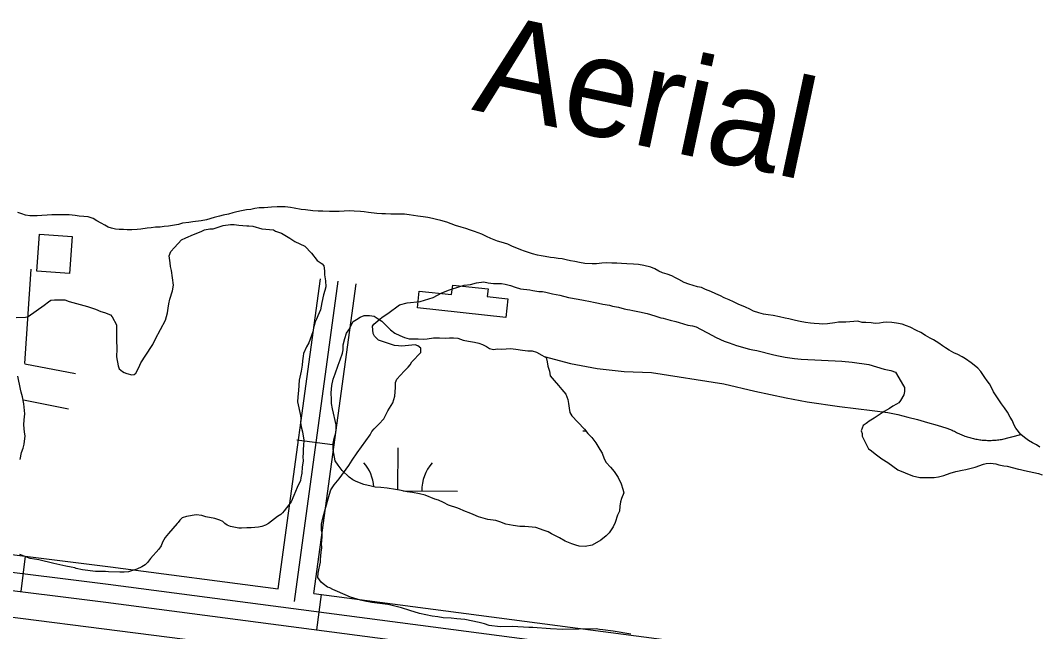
# Model space of a CAD drawing. Extents: x 3161514 to 3199414, y 831166 to 856601.
# Drawn here: x 3186690 to 3187544, y 849984 to 850496 of the extents above; entities that cross this region are included whole.
import ezdxf

# ---------------------------------------------------------------- set-up
doc = ezdxf.new("R2010")
doc.units = 0
for name, color, linetype in [('V-BLDG-OTLN', 7, 'Continuous'), ('V-LEVE-TOET', 7, 'Continuous'), ('V-RIVR-IDEN', 7, 'Continuous'), ('V-ROAD-CNTR', 7, 'Continuous'), ('V-SITE-VEGE', 7, 'Continuous'), ('V-TOPO-SHOR', 7, 'Continuous'), ('V-WETL-SWMP', 7, 'Continuous')]:
    doc.layers.add(name, color=color, linetype=linetype)

msp = doc.modelspace()

# ---------------------------------------------------------------- linework, layer by layer
at = {"layer": 'V-BLDG-OTLN'}
for points in [[(3186704.25, 850285.64), (3186706.49, 850316.62), (3186733.69, 850314.67), (3186731.46, 850283.68)], [(3187097.06, 850246.78), (3187022.99, 850254.86), (3187024.54, 850269.01), (3187051.6, 850266.06), (3187052.47, 850274.07), (3187082.15, 850270.83), (3187081.46, 850264.47), (3187098.79, 850262.58)]]:
    msp.add_lwpolyline(points, close=True, dxfattribs=at)
at = {"layer": 'V-LEVE-TOET'}
msp.add_lwpolyline([(3185951.2, 850091.7), (3186111.35, 850071.25), (3186287.91, 850050.19), (3186449.48, 850029.4), (3186609.3, 850005.42), (3186841.67, 849975.68), (3187036.96, 849950.67), (3187260.69, 849919.64), (3187537.4, 849882.56), (3187802.62, 849847.53), (3188050, 849815.58), (3188330.04, 849780.64), (3188583.22, 849752.07), (3188616.24, 849747.31), (3188633.9, 849745.47), (3188641.14, 849745.34)], dxfattribs=at)
at = {"layer": 'V-ROAD-CNTR'}
for p, q in [((3186694.27, 850208.45), (3186699.57, 850287.45)), ((3186922.05, 850144.5), (3186951.77, 850140.44)), ((3186694.39, 850046.98), (3186690.68, 850017.21)), ((3186942.42, 850014.88), (3186938.51, 849985.14))]:
    msp.add_line(p, q, dxfattribs=at)
for points in [[(3186906.31, 850019.62), (3186941.81, 850279.21)], [(3186919.98, 850008.84), (3186956.67, 850277.18)], [(3186936.06, 850015.71), (3186971.54, 850275.15)], [(3186694.3, 850208.08), (3186736.48, 850199.92)], [(3189447.95, 850001.11), (3189429.03, 849814.74), (3189421.01, 849784.3), (3189410.76, 849768.58), (3189395.7, 849753.5), (3189376.92, 849738.22), (3189354.56, 849730.31), (3189331.81, 849725.77), (3189310.92, 849725.82), (3189278.4, 849725.99), (3188774.4, 849761.57), (3188653.34, 849778.2), (3188289.25, 849825.21), (3187591.11, 849914.58), (3186763.92, 850023.19), (3186125.42, 850102.82), (3185403.58, 850201)], [(3185401.56, 850186.13), (3186123.48, 850087.95), (3186762.01, 850008.31), (3187589.18, 849899.7), (3188287.33, 849810.33), (3188617.05, 849767.76)], [(3186693.09, 850177.76), (3186730.79, 850170.47)], [(3186683.41, 850048.35), (3186765.82, 850038.07), (3186906.31, 850019.62)], [(3186936.06, 850015.71), (3187593.04, 849929.45), (3187874.08, 849893.48)]]:
    msp.add_lwpolyline(points, dxfattribs=at)
at = {"layer": 'V-SITE-VEGE'}
for points in [[(3186686.89, 850246.9), (3186694.82, 850247.18), (3186696.91, 850247.66), (3186710.38, 850257.06), (3186713.86, 850260.11), (3186715.95, 850261.29), (3186718.98, 850261.77), (3186722.24, 850261.79), (3186727.6, 850261.58), (3186731.34, 850260.21), (3186746.75, 850256.1), (3186753.29, 850253.81), (3186757.73, 850251.97), (3186761, 850251.05), (3186765.9, 850248.98), (3186767.31, 850247.36), (3186770.85, 850240.62), (3186770.92, 850228.03), (3186771.19, 850220.57), (3186771, 850213.81), (3186772.2, 850206.36), (3186773.15, 850203.8), (3186775.96, 850201.72), (3186777.36, 850200.79), (3186779.7, 850199.88), (3186783.9, 850198.73), (3186785.77, 850198.98), (3186787.16, 850200.15), (3186789.69, 850205.06), (3186791.31, 850208.8), (3186800.32, 850222.6), (3186801.48, 850224.24), (3186803.55, 850228.91), (3186811.85, 850244.58), (3186813.68, 850250.65), (3186814.12, 850254.62), (3186814.8, 850258.35), (3186815.71, 850262.32), (3186817.77, 850269.32), (3186818.68, 850273.99), (3186816.98, 850286.1), (3186816.03, 850289.59), (3186816.01, 850292.62), (3186815.04, 850298.44), (3186816.42, 850302.18), (3186819.43, 850305.46), (3186825.46, 850312.02), (3186828.94, 850313.67), (3186835.46, 850316.51), (3186841.73, 850318.88), (3186844.52, 850320.29), (3186849.19, 850321.01), (3186851.98, 850321.03), (3186860.35, 850323.88), (3186866.41, 850324.84), (3186869.44, 850324.62), (3186873.41, 850324.18), (3186880.17, 850323.75), (3186881.8, 850323.76), (3186885.07, 850323.32), (3186892.54, 850321.26), (3186902.33, 850320.15), (3186904.2, 850319.23), (3186909.11, 850317.62), (3186916.13, 850313.23)], [(3186916.13, 850313.23), (3186920.34, 850310.46), (3186928.52, 850306.54), (3186934.15, 850300.75), (3186939.08, 850294.72), (3186943.29, 850291.94), (3186944.46, 850290.08), (3186945.19, 850285.89), (3186945.21, 850282.63), (3186945.93, 850277.5), (3186946.19, 850272.61), (3186945.28, 850269.57), (3186944.37, 850265.84), (3186943, 850259.54), (3186941.87, 850253.24), (3186939.57, 850248.33), (3186938.42, 850245.53), (3186937.27, 850243.19), (3186936.59, 850240.16), (3186935.9, 850238.05), (3186935.22, 850234.79), (3186932.01, 850225.68), (3186930.16, 850222.41), (3186927.63, 850216.79), (3186927.18, 850214.46), (3186926.73, 850210.49), (3186926.52, 850207), (3186925.61, 850201.86), (3186924.02, 850194.39), (3186923.37, 850185.77), (3186922.7, 850180.4), (3186922.5, 850176.2), (3186924.89, 850164.8), (3186925.37, 850162), (3186925.16, 850158.97), (3186925.65, 850155.24), (3186926.83, 850151.05), (3186927.81, 850144.07), (3186927.6, 850139.64), (3186927.15, 850136.6), (3186927.17, 850133.34), (3186926.95, 850130.08), (3186927.2, 850126.81), (3186926.3, 850121.45), (3186926.1, 850116.55), (3186925.19, 850112.58)], [(3187004.71, 850188.32), (3187004.46, 850192.29), (3187005.84, 850195.09), (3187011.86, 850201.88), (3187015.11, 850205.17), (3187016.73, 850207.27), (3187018.35, 850209.61), (3187025.76, 850217.58), (3187025.74, 850221.08), (3187023.16, 850223.16), (3187021.06, 850223.85), (3187009.88, 850222.85), (3187007.08, 850223.07), (3187003.81, 850223.52), (3186990.27, 850227.87), (3186986.99, 850231.11), (3186985.81, 850233.44), (3186985.31, 850239.73), (3186986.46, 850241.37), (3186991.34, 850245.36), (3186993.43, 850247), (3186998.07, 850250.29), (3187008.05, 850257.57), (3187014.34, 850259.01), (3187025.29, 850260.24), (3187036.22, 850263.56), (3187043.43, 850267.56), (3187049.94, 850270.16), (3187058.55, 850272.78), (3187062.04, 850273.96), (3187067.4, 850274.46), (3187072.29, 850275.88), (3187078.58, 850276.62), (3187082.31, 850275.94), (3187086.74, 850275.27), (3187093.27, 850275.31), (3187096.53, 850274.86), (3187100.97, 850273.71), (3187104.71, 850272.34), (3187109.38, 850270.96), (3187117.08, 850270.08), (3187119.64, 850269.39), (3187124.54, 850268.72), (3187127.81, 850268.74), (3187130.61, 850268.06), (3187135.97, 850266.69), (3187142.28, 850265.56), (3187149.51, 850263.73), (3187157.68, 850262.15), (3187162.11, 850261.47), (3187167.95, 850260.34), (3187170.52, 850259.66), (3187174.72, 850258.75), (3187178.22, 850258.07), (3187183.82, 850257.17), (3187186.38, 850256.48), (3187191.29, 850255.58), (3187195.95, 850254.2), (3187198.76, 850253.52), (3187200.85, 850253.3), (3187203.42, 850252.85), (3187209.02, 850251.48), (3187215.32, 850250.12), (3187221.86, 850248.29), (3187226.77, 850246.69), (3187228.87, 850246.23), (3187234.7, 850244.63), (3187239.37, 850243.49), (3187242.18, 850242.58), (3187245.91, 850241.67), (3187249.41, 850240.52), (3187253.38, 850239.84), (3187256.42, 850238.93), (3187259.92, 850237.08), (3187266, 850234.09), (3187273.25, 850230.17), (3187279.79, 850226.94), (3187284, 850225.56), (3187290.3, 850223.27), (3187301.04, 850220.3), (3187303.84, 850219.85), (3187307.11, 850219.17), (3187321.35, 850215.52), (3187325.32, 850214.61), (3187330.92, 850213.71), (3187338.85, 850212.59), (3187344.45, 850211.92), (3187378.26, 850210.24), (3187387.12, 850209.36), (3187401.12, 850207.35), (3187413.96, 850203.69), (3187419.33, 850202.55), (3187423.3, 850201.17), (3187429.89, 850189.56), (3187430.83, 850188.16), (3187430.85, 850184.9), (3187430.17, 850182.1), (3187427.63, 850177.42), (3187426.01, 850175.32), (3187424.15, 850174.14), (3187421.13, 850172.49)], [(3186690.13, 850128.04), (3186691.26, 850133.64), (3186692.64, 850137.38), (3186693.55, 850140.88), (3186694.45, 850147.65), (3186693.96, 850150.9), (3186693.46, 850156.96), (3186693.67, 850161.16), (3186694.11, 850166.29), (3186693.36, 850174.45), (3186692.17, 850180.27), (3186691.21, 850184.22), (3186690.5, 850186.78), (3186688.33, 850197.73)], [(3187201.69, 849981.51), (3187186.99, 849983.98), (3187178.12, 849985.33), (3187175.33, 849985.55), (3187172.52, 849986), (3187158.07, 849985.92), (3187144.79, 849985.61), (3187134.53, 849986.02), (3187119.6, 849987.1), (3187116.11, 849987.08), (3187102.58, 849987.94), (3187092.33, 849987.88), (3187083, 849988.99), (3187079.03, 849990.37), (3187074.59, 849991.51), (3187062.69, 849994.01), (3187055.92, 849994.43), (3187051.26, 849994.87), (3187044.5, 849995.3), (3187040.06, 849996.21), (3187035.4, 849996.65), (3187024.66, 849998.92), (3187016.49, 850001.44), (3187009.48, 850003.73), (3187007.39, 850004.18), (3187000.61, 850006.01), (3186998.28, 850006.46), (3186984.75, 850008.25), (3186978.92, 850009.15), (3186975.18, 850010.06), (3186966.78, 850012.58), (3186956.03, 850017.41), (3186952.05, 850019.02), (3186949.71, 850020.41), (3186947.61, 850021.1), (3186944.1, 850023.87), (3186942.46, 850025.03), (3186939.64, 850028.98), (3186939.86, 850032.71), (3186940.31, 850035.51), (3186941.22, 850039.47), (3186941.67, 850042.04), (3186941.89, 850044.14), (3186942.32, 850050.21), (3186942.77, 850053.94), (3186942.75, 850057.43), (3186942.97, 850059.53), (3186943.18, 850063.5), (3186943.16, 850066.29), (3186942.68, 850068.85), (3186942.65, 850073.75), (3186943.79, 850078.65), (3186946.3, 850087.99), (3186948.13, 850094.99), (3186949.27, 850098.96), (3186950.42, 850102.46), (3186953.19, 850106.68), (3186957.36, 850111.83), (3186965.45, 850122.83), (3186968.23, 850127.28), (3186972.62, 850133.36), (3186983.25, 850148.57), (3186984.88, 850151.38), (3186986.73, 850153.49), (3186990.67, 850157.47), (3186994.84, 850161.93), (3186998.3, 850168.7), (3187002.22, 850175.26), (3187004.05, 850181.09), (3187004.71, 850188.32)], [(3187421.13, 850172.49), (3187418.34, 850170.61), (3187413.93, 850168.02), (3187405.33, 850162.61), (3187401.39, 850160.03), (3187399.99, 850158.85), (3187398.83, 850158.15), (3187396.28, 850156.27), (3187394.44, 850151.83)], [(3187394.44, 850151.83), (3187395.38, 850149.73), (3187395.4, 850147.4), (3187400.82, 850136.94), (3187402.22, 850136.02), (3187407.37, 850131.85), (3187411.82, 850128.38), (3187416.97, 850125.38), (3187425.39, 850119.37), (3187437.54, 850114.31), (3187443.61, 850112.94), (3187452.94, 850112.76), (3187455.73, 850112.78), (3187459.23, 850113.26), (3187463.88, 850114.46), (3187469, 850116.58), (3187473.89, 850117.78), (3187475.28, 850118.25), (3187479.24, 850118.97), (3187482.27, 850119.45), (3187489.95, 850121.59), (3187496.93, 850123.97), (3187499.26, 850124.68), (3187502.75, 850124.93), (3187507.42, 850124.26), (3187509.98, 850123.57), (3187513.95, 850122.66), (3187516.75, 850122.21), (3187526.33, 850119.7), (3187527.96, 850119.48), (3187531.46, 850118.57), (3187543.13, 850116.07), (3187546.16, 850115.15)], [(3186925.19, 850112.58), (3186924.96, 850110.25), (3186922.2, 850104.41), (3186919.44, 850097.86), (3186917.14, 850092.49), (3186915.29, 850089.91), (3186911.35, 850085), (3186909.96, 850083.12), (3186908.58, 850081.95), (3186905.79, 850080.3), (3186898.13, 850074.43), (3186895.8, 850073.02), (3186892.78, 850071.84), (3186889.75, 850071.35), (3186883.7, 850070.62), (3186879.97, 850070.6), (3186875.54, 850070.34), (3186873.44, 850070.33), (3186866.44, 850071.69), (3186863.64, 850072.84), (3186861.76, 850074.23), (3186860.12, 850075.85), (3186857.55, 850077.23), (3186853.35, 850078.61), (3186845.88, 850079.96), (3186842.38, 850080.88), (3186837.71, 850081.55), (3186829.56, 850080.11), (3186825.84, 850078.92), (3186823.99, 850077.04), (3186822.6, 850075.17), (3186821.67, 850074.23), (3186814.49, 850066.03), (3186811.71, 850062.52), (3186809.4, 850058.78), (3186808.25, 850055.51), (3186806.41, 850052.7), (3186799.46, 850044.97), (3186796.91, 850041.69), (3186794.83, 850039.58), (3186792.04, 850037.94), (3186788.08, 850036.05), (3186781.1, 850033.68), (3186777.37, 850033.42), (3186773.65, 850033.4), (3186764.32, 850033.82), (3186761.76, 850034.03), (3186759.19, 850034.02), (3186755.46, 850034.23), (3186753.36, 850033.99), (3186742.4, 850035.56), (3186737.26, 850036.69), (3186736.1, 850037.15), (3186733.06, 850037.83), (3186728.4, 850038.51), (3186718.36, 850040.78), (3186705.75, 850043.97), (3186698.75, 850045.1), (3186690.11, 850048.32)]]:
    msp.add_lwpolyline(points, dxfattribs=at)
at = {"layer": 'V-TOPO-SHOR'}
msp.add_line((3187511.98, 850144.71), (3187528.17, 850148.98), dxfattribs=at)
for points in [[(3187218.44, 850288.95), (3187212.5, 850290.52), (3187208, 850291.14), (3187203.98, 850291.44), (3187198.37, 850291.88), (3187193.87, 850292.02), (3187190.02, 850292.32), (3187185.85, 850292.46), (3187181.67, 850292.59), (3187177.5, 850292.41), (3187173.01, 850291.9), (3187169.16, 850291.72), (3187163.06, 850292.17), (3187158.72, 850292.94), (3187154.86, 850293.88), (3187151.01, 850294.34), (3187147.47, 850295.29), (3187144.1, 850296.07), (3187140.89, 850296.21), (3187137.51, 850296.83), (3187134.3, 850297.14), (3187129.8, 850297.92), (3187126.59, 850298.54), (3187123.54, 850299.17), (3187119.36, 850300.1), (3187115.98, 850301.37), (3187112.61, 850302.47), (3187109.55, 850303.58), (3187106.33, 850305.01), (3187102.47, 850306.43), (3187098.61, 850308.17), (3187093.15, 850309.91), (3187090.09, 850310.69), (3187084.3, 850312.91), (3187080.92, 850314.65), (3187076.9, 850316.56), (3187073.68, 850317.66), (3187070.63, 850318.93), (3187067.41, 850320.03), (3187063.55, 850321.45), (3187059.69, 850322.56), (3187054.71, 850323.97), (3187051.33, 850325.4), (3187047.47, 850326.66), (3187042.65, 850328.08), (3187038.95, 850329.02), (3187035.58, 850329.64), (3187031.56, 850330.58), (3187027.71, 850331.2), (3187023.37, 850331.66), (3187016.14, 850332.74), (3187012.13, 850333.36), (3187008.6, 850333.5), (3187004.9, 850333.48), (3187000.57, 850333.46), (3186996.08, 850333.59), (3186993.03, 850333.73), (3186988.85, 850334.03), (3186981.95, 850334.8), (3186978.41, 850335.26), (3186975.2, 850335.56), (3186969.9, 850336.01), (3186966.21, 850336.15), (3186961.72, 850335.97), (3186957.39, 850335.62), (3186953.86, 850335.76), (3186949.36, 850335.73), (3186943.75, 850336.03), (3186939.73, 850336), (3186935.4, 850336.3), (3186929.3, 850336.91), (3186925.6, 850337.37), (3186919.82, 850338.46), (3186916.77, 850339.08), (3186912.27, 850339.54), (3186908.74, 850339.52), (3186905.53, 850339.5), (3186900.72, 850339.15), (3186897.67, 850338.97), (3186894.62, 850338.8), (3186890.29, 850338.61), (3186886.92, 850338.11), (3186883.55, 850337.45), (3186879.7, 850337.11), (3186875.54, 850336.28), (3186871.69, 850335.3), (3186868.48, 850334.48), (3186864.8, 850333.49), (3186860.31, 850332.67), (3186857.26, 850331.85), (3186852.62, 850330.54), (3186846.21, 850328.57), (3186841.88, 850327.75), (3186834.99, 850327.07), (3186831.46, 850326.56), (3186826.33, 850325.73), (3186822.8, 850324.75), (3186817.83, 850323.92), (3186814.62, 850323.42), (3186810.77, 850323.08), (3186807.41, 850322.42)], [(3186807.41, 850322.42), (3186803.71, 850322.4), (3186799.87, 850321.89), (3186796.66, 850321.56), (3186791.21, 850320.88), (3186788.16, 850320.7), (3186783.67, 850320.36), (3186779.81, 850320.33), (3186776.77, 850320.48), (3186773.23, 850320.62), (3186770.02, 850320.92), (3186766.81, 850321.71), (3186763.91, 850322.65), (3186761.18, 850324.08), (3186758.12, 850325.83), (3186754.58, 850327.9), (3186751.52, 850329.64), (3186747.18, 850331.06), (3186743.64, 850331.53), (3186739.63, 850331.82), (3186736.26, 850332.29), (3186731.28, 850332.9), (3186726.46, 850332.87), (3186722.61, 850332.85), (3186716.67, 850332.82), (3186712.98, 850332.64), (3186708.49, 850332.29), (3186704.48, 850331.95), (3186701.43, 850331.93), (3186698.38, 850331.91), (3186694.85, 850332.7), (3186691.63, 850333.64), (3186688.42, 850334.91)], [(3187544.12, 850138.32), (3187541.38, 850140.07), (3187538.16, 850141.98), (3187534.78, 850143.89), (3187531.4, 850146.28), (3187528.17, 850148.98), (3187524.13, 850154.26), (3187522.35, 850157.3), (3187521.21, 850160.18), (3187519.42, 850163.38), (3187517.15, 850167.54), (3187514.73, 850171.06), (3187512.14, 850174.57), (3187510.52, 850177.13), (3187508.25, 850180.33), (3187505.5, 850184.65), (3187503.88, 850187.69), (3187502.09, 850191.37), (3187500.15, 850193.92), (3187498.05, 850196.64), (3187494.81, 850201.6), (3187492.23, 850204.47), (3187489.17, 850206.86), (3187486.59, 850208.93), (3187482.07, 850212.28), (3187479.18, 850213.87), (3187475.64, 850215.77), (3187472.26, 850217.36), (3187468.39, 850219.58), (3187465.33, 850221.33), (3187462.6, 850223.08), (3187459.53, 850225.31), (3187455.19, 850228.01), (3187452.29, 850229.6), (3187448.42, 850231.83), (3187444.4, 850234.37), (3187440.86, 850235.96), (3187435.55, 850238.66), (3187432.49, 850239.92), (3187428.95, 850241.35), (3187424.29, 850242.12), (3187420.28, 850242.74), (3187416.1, 850242.88), (3187412.9, 850242.7), (3187409.85, 850242.04), (3187406.16, 850241.86), (3187402.95, 850242.32), (3187398.61, 850242.62), (3187395.4, 850242.76), (3187391.86, 850243.71), (3187388.5, 850243.37), (3187385.13, 850243.35), (3187381.76, 850243.01), (3187375.66, 850242.81), (3187372.61, 850242.47), (3187366.36, 850241.48), (3187362.51, 850241.13), (3187359.3, 850241.44), (3187355.28, 850241.73), (3187352.23, 850242.04), (3187347.9, 850242.66), (3187343.4, 850243.59), (3187339.7, 850244.21), (3187334.08, 850245.63), (3187331.02, 850246.41), (3187326.21, 850247.51), (3187320.74, 850248.6), (3187316.57, 850249.06), (3187312.71, 850249.68), (3187308.85, 850250.78), (3187304.51, 850252.2), (3187301.29, 850253.79), (3187297.59, 850255.53), (3187291.64, 850258.07), (3187287.78, 850259.97), (3187283.92, 850261.55), (3187279.89, 850263.46), (3187276.67, 850264.88), (3187272.81, 850266.79), (3187268.63, 850268.69), (3187264.29, 850270.43), (3187260.91, 850271.86), (3187257.53, 850272.64), (3187253.84, 850273.58), (3187250.14, 850274.84), (3187246.44, 850276.27), (3187241.93, 850278.81), (3187239.2, 850280.08), (3187235.98, 850281.66), (3187232.12, 850283.09), (3187228.1, 850284.35), (3187225.04, 850285.77), (3187221.66, 850287.52), (3187218.44, 850288.95)], [(3187129.01, 850214.29), (3187151.02, 850208.34), (3187173.41, 850204.09), (3187196.07, 850201.58), (3187218.85, 850200.82), (3187218.85, 850200.82), (3187279.6, 850191.23), (3187279.6, 850191.23), (3187305.64, 850185.21), (3187331.77, 850179.63), (3187349.21, 850176.17), (3187349.21, 850176.17), (3187376.47, 850172.27), (3187403.79, 850168.84), (3187416.95, 850167.35), (3187416.95, 850167.35), (3187425.28, 850165.49), (3187433.58, 850163.48), (3187441.83, 850161.33), (3187450.06, 850159.03), (3187458.24, 850156.6), (3187466.38, 850154.02), (3187470.74, 850152.57), (3187470.74, 850152.57), (3187471.66, 850152.04), (3187472.6, 850151.51), (3187473.54, 850151), (3187474.49, 850150.51), (3187475.46, 850150.04), (3187476.42, 850149.58), (3187477.4, 850149.14), (3187478.38, 850148.72), (3187479.38, 850148.31), (3187480.37, 850147.92), (3187481.38, 850147.55), (3187482.39, 850147.2), (3187483.41, 850146.86), (3187484.43, 850146.54), (3187485.46, 850146.24), (3187486.49, 850145.96), (3187487.53, 850145.7), (3187488.57, 850145.45), (3187489.62, 850145.22), (3187490.67, 850145.01), (3187491.72, 850144.82), (3187492.78, 850144.65), (3187493.84, 850144.49), (3187494.9, 850144.36), (3187495.97, 850144.24), (3187497.03, 850144.14), (3187498.1, 850144.06), (3187499.17, 850144), (3187500.24, 850143.95), (3187501.31, 850143.93), (3187502.38, 850143.92), (3187503.45, 850143.94), (3187504.52, 850143.97), (3187505.59, 850144.02), (3187506.66, 850144.09), (3187507.73, 850144.18), (3187508.8, 850144.28), (3187509.86, 850144.41), (3187510.92, 850144.55), (3187511.98, 850144.71), (3187511.98, 850144.71)]]:
    msp.add_lwpolyline(points, dxfattribs=at)
at = {"layer": 'V-WETL-SWMP'}
for p, q in [((3187161.35, 850151.98), (3187163.81, 850151.97)), ((3187006.62, 850102.49), (3187006.72, 850137.66)), ((3187011.1, 850101.65), (3187056.62, 850101.52))]:
    msp.add_line(p, q, dxfattribs=at)
for points in [[(3186951.88, 850170.47), (3186951.11, 850174.88), (3186951.1, 850178.19), (3186950.7, 850183.71), (3186951.4, 850189.96), (3186952.47, 850195.12), (3186953.92, 850199.54), (3186956.45, 850206.91), (3186958.27, 850211.34), (3186960.07, 850216.87), (3186960.79, 850219.81), (3186960.77, 850223.86), (3186962.21, 850229.39), (3186963.66, 850233.81), (3186965.48, 850236.39), (3186969.12, 850243.4), (3186972.05, 850245.26), (3186974.98, 850247.11), (3186978.29, 850248.6), (3186982.7, 850248.63), (3186986.75, 850247.92), (3186990.08, 850245.73), (3186993.03, 850243.91), (3186998.21, 850238.79), (3187000.43, 850236.59), (3187004.12, 850233.67), (3187008.18, 850231.85), (3187012.24, 850230.04), (3187015.92, 850228.95), (3187023.65, 850229), (3187027.69, 850228.65), (3187031, 850229.04), (3187036.52, 850229.81), (3187041.3, 850229.83), (3187046.08, 850229.49), (3187049.76, 850229.88), (3187053.07, 850229.9), (3187056.75, 850229.55), (3187061.18, 850227.74), (3187065.59, 850227.03), (3187070.75, 850226.32), (3187074.43, 850225.24), (3187077.38, 850224.15), (3187080.7, 850222.7), (3187083.29, 850220.87), (3187086.6, 850220.16), (3187089.91, 850220.54), (3187093.59, 850220.19), (3187097.27, 850220.58), (3187100.94, 850220.97), (3187105.36, 850220.26), (3187110.88, 850219.56), (3187115.3, 850218.84), (3187118.98, 850218.87), (3187122.67, 850217.78), (3187127.09, 850215.23), (3187129.01, 850214.29), (3187130.78, 850213.42), (3187131.54, 850209.74), (3187132.29, 850206.07), (3187133.42, 850202.03), (3187134.18, 850197.98), (3187137.51, 850193.96), (3187141.21, 850189.93), (3187143.81, 850186.63), (3187147.14, 850182.61), (3187149.01, 850178.2), (3187149.39, 850174.89), (3187150.15, 850170.85), (3187150.54, 850167.18), (3187152.39, 850164.61), (3187157.21, 850159.12), (3187162.76, 850153.27), (3187165.72, 850149.6), (3187169.05, 850146.31), (3187172.39, 850141.92), (3187175.73, 850136.42), (3187177.59, 850133.12), (3187179.45, 850128.34), (3187180.94, 850125.41), (3187184.64, 850121.39), (3187187.61, 850117.72), (3187190.94, 850112.96), (3187193.55, 850107.46), (3187195.05, 850103.05), (3187195.8, 850100.11), (3187193.99, 850095.32), (3187192.9, 850092.37), (3187192.55, 850088.69), (3187192.21, 850084.64), (3187190.39, 850081.32), (3187188.58, 850075.06), (3187186.76, 850071.37), (3187183.48, 850066.57), (3187180.92, 850063.98), (3187176.53, 850060.27), (3187169.19, 850056.19), (3187163.31, 850055.05), (3187158.53, 850055.39), (3187155.58, 850056.11), (3187152.26, 850057.19)], [(3187152.26, 850057.19), (3187146.73, 850059.37), (3187141.94, 850062.29), (3187135.29, 850065.56), (3187132.34, 850067.38), (3187129.02, 850068.47), (3187122.02, 850071), (3187112.82, 850071.69), (3187108.77, 850071.66), (3187103.25, 850072.73), (3187096.99, 850073.8), (3187091.83, 850075.61), (3187088.51, 850076.7), (3187081.89, 850077.77), (3187074.15, 850079.93), (3187069.72, 850081.74), (3187066.41, 850083.2), (3187063.09, 850084.28), (3187056.82, 850087.19), (3187049.08, 850089.72), (3187044.65, 850091.9), (3187040.6, 850093.72), (3187037.65, 850094.81), (3187029.54, 850098.07), (3187024.75, 850099.15), (3187018.85, 850100.22), (3187014.44, 850100.93), (3187007.81, 850102.36), (3187004.49, 850102.71), (3186997.5, 850103.78), (3186992.34, 850104.48), (3186987.56, 850104.82), (3186984.25, 850105.54), (3186977.98, 850106.97), (3186971.71, 850109.52), (3186968.76, 850110.97), (3186965.81, 850113.16), (3186959.89, 850118.65), (3186956.56, 850123.04), (3186953.96, 850126.7), (3186952.82, 850132.95), (3186952.44, 850136.26), (3186952.41, 850141.41), (3186953.12, 850145.46), (3186954.56, 850150.25), (3186954.91, 850153.56), (3186954.89, 850156.88), (3186951.88, 850170.47)]]:
    msp.add_lwpolyline(points, dxfattribs=at)
for centre, start, end in [((3186951.38, 850102.29), 4.49163, 40.61354), ((3187061.86, 850101.98), 139.06988, 180.61354)]:
    msp.add_arc(centre, 35.25, start, end, dxfattribs=at)

# ---------------------------------------------------------------- texts
at = {"layer": 'V-RIVR-IDEN'}
msp.add_text('Aerial', height=83, rotation=348, dxfattribs=at).set_placement((3187067.73, 850421.07))

doc.saveas('drawing.dxf')
